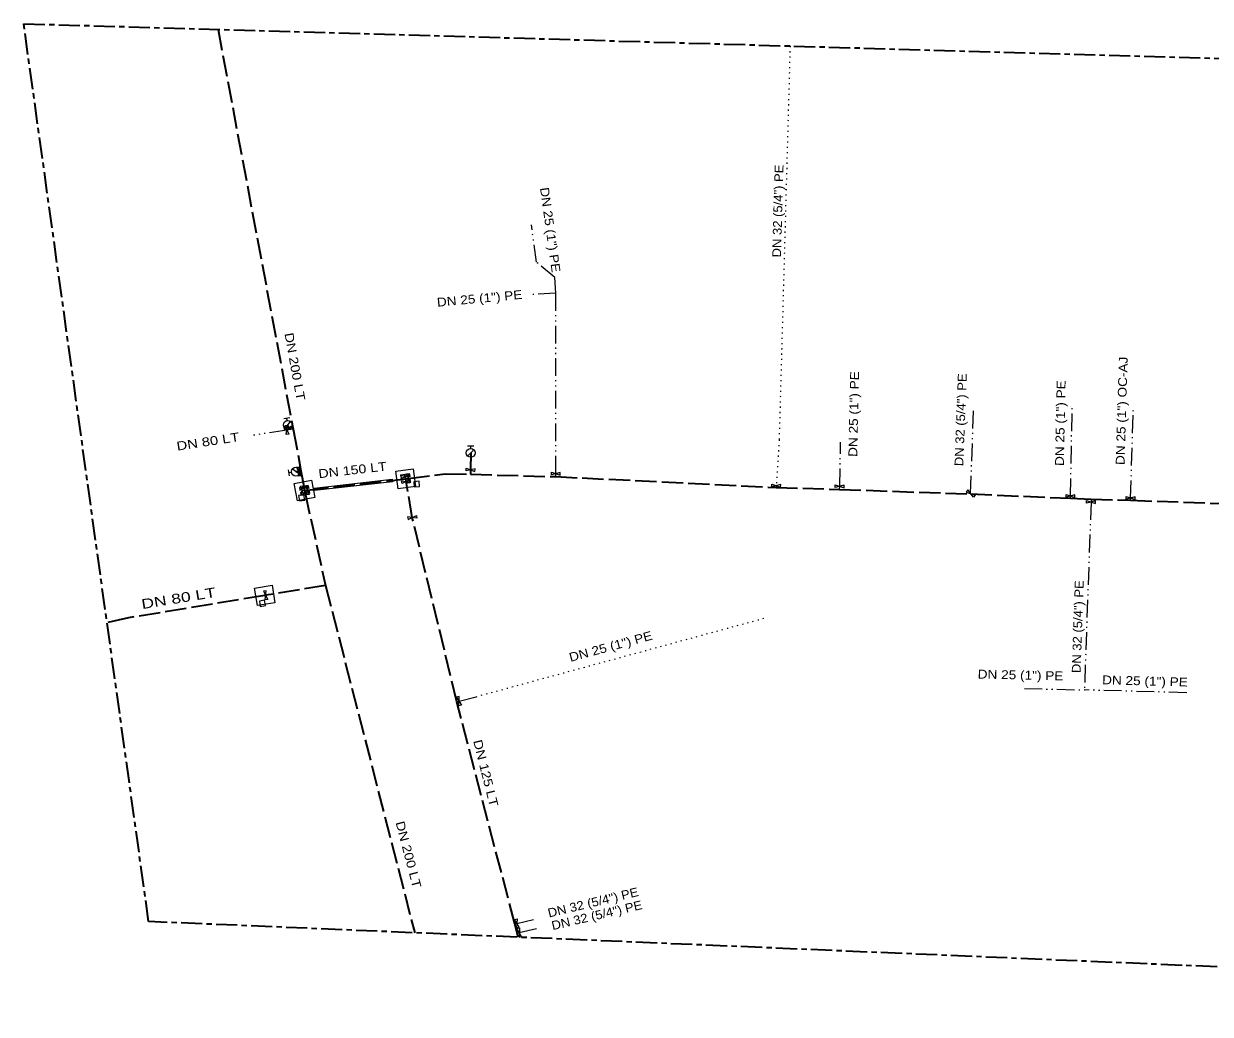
# Model space of a CAD drawing. Extents: x -640241 to -639979, y -1041483 to -1041371.
# Drawn here: x -640241 to -640106.8, y -1041482.8 to -1041370.7 of the extents above; entities that cross this region are included whole.
import ezdxf
from ezdxf.enums import TextEntityAlignment as Align

# ---------------------------------------------------------------- set-up
doc = ezdxf.new("R2010")
doc.units = 0
doc.header["$LTSCALE"] = 0.4
for name, pattern in [('DASH_DOUBLE_DOT', [9.2, 5, -1.2, 0.3, -1.2, 0.3, -1.2]), ('DOTTED', [1.5, 0.3, -1.2]), ('LONG_DASH_SHORT_DASH', [9.9, 6, -1.2, 1.5, -1.2]), ('LONG_DASHED', [7.5, 6, -1.5])]:
    doc.linetypes.add(name, pattern=pattern)
for name, color, linetype, lineweight in [('1', 7, 'LONG_DASH_SHORT_DASH', 35), ('10', 7, 'Continuous', 13), ('13', 7, 'Continuous', 13), ('21', 7, 'LONG_DASHED', 35), ('22', 7, 'DASH_DOUBLE_DOT', 35), ('32', 7, 'DASH_DOUBLE_DOT', 13), ('51', 7, 'Continuous', 25)]:
    doc.layers.add(name, color=color, linetype=linetype, lineweight=lineweight)
doc.layers.add('29', color=7, linetype='Continuous')
doc.layers.add('39', color=7, linetype='Continuous')

msp = doc.modelspace()

# ---------------------------------------------------------------- linework, layer by layer
at = {"layer": '1'}
msp.add_lwpolyline([(-639990.066, -1041378.027), (-639979.473, -1041482.75), (-640226.879, -1041472.267), (-640241.004, -1041370.744)], close=True, dxfattribs=at)
at = {"layer": '10'}
for p, q in [((-640211.613, -1041415.38), (-640210.921, -1041415.278)), ((-640211.448, -1041416.523), (-640210.853, -1041415.719)), ((-640211.224, -1041415.626), (-640211.267, -1041415.329)), ((-640190.815, -1041418.47), (-640190.115, -1041418.47)), ((-640190.465, -1041418.77), (-640190.465, -1041418.47)), ((-640190.819, -1041419.624), (-640190.112, -1041418.917)), ((-640209.813, -1041421.681), (-640210.626, -1041421.099)), ((-640210.952, -1041421.866), (-640211.066, -1041421.175)), ((-640210.713, -1041421.472), (-640211.009, -1041421.521)), ((-640198.401, -1041421.751), (-640197.415, -1041421.585)), ((-640198.401, -1041421.751), (-640198.359, -1041421.998)), ((-640197.415, -1041421.585), (-640197.373, -1041421.831))]:
    msp.add_line(p, q, dxfattribs=at)
for points in [[(-640211.554, -1041416.618), (-640210.605, -1041416.182), (-640210.564, -1041416.479), (-640211.596, -1041416.321)], [(-640211.474, -1041416.219), (-640211.026, -1041417.161), (-640211.322, -1041417.207), (-640211.178, -1041416.173)], [(-640209.672, -1041421.824), (-640210.148, -1041420.895), (-640209.853, -1041420.841), (-640209.967, -1041421.879)], [(-640196.959, -1041421.085), (-640196.69, -1041423.067), (-640198.672, -1041423.336), (-640198.941, -1041421.354)], [(-640189.969, -1041421.092), (-640190.991, -1041421.308), (-640190.966, -1041421.009), (-640189.994, -1041421.391)], [(-640210.424, -1041422.727), (-640208.46, -1041422.347), (-640208.08, -1041424.311), (-640210.044, -1041424.691)], [(-640198.334, -1041422.149), (-640197.398, -1041421.686), (-640197.348, -1041421.982), (-640198.384, -1041421.853)], [(-640197.297, -1041422.281), (-640198.233, -1041422.743), (-640198.283, -1041422.447), (-640197.247, -1041422.577)], [(-640197.734, -1041421.696), (-640197.306, -1041422.648), (-640197.603, -1041422.687), (-640197.436, -1041421.657)], [(-640180.335, -1041421.481), (-640181.346, -1041421.739), (-640181.334, -1041421.439), (-640180.347, -1041421.781)], [(-640209.77, -1041423.468), (-640208.84, -1041422.993), (-640208.786, -1041423.288), (-640209.824, -1041423.173)], [(-640209.755, -1041423.085), (-640209.343, -1041424.043), (-640209.641, -1041424.078), (-640209.457, -1041423.05)], [(-640209.664, -1041424.047), (-640208.734, -1041423.572), (-640208.68, -1041423.867), (-640209.718, -1041423.752)], [(-640209.153, -1041423.004), (-640208.741, -1041423.964), (-640209.039, -1041423.998), (-640208.855, -1041422.97)], [(-640155.414, -1041422.861), (-640156.426, -1041423.118), (-640156.413, -1041422.819), (-640155.427, -1041423.161)], [(-640148.244, -1041422.921), (-640149.256, -1041423.178), (-640149.243, -1041422.879), (-640148.257, -1041423.221)], [(-640134.431, -1041423.699), (-640133.446, -1041424.041), (-640133.621, -1041424.283), (-640134.257, -1041423.456)], [(-640122.145, -1041424.029), (-640123.155, -1041424.292), (-640123.144, -1041423.992), (-640122.156, -1041424.329)], [(-640119.825, -1041424.709), (-640120.835, -1041424.972), (-640120.825, -1041424.672), (-640119.836, -1041425.008)], [(-640115.344, -1041424.248), (-640116.355, -1041424.511), (-640116.344, -1041424.211), (-640115.355, -1041424.548)], [(-640197.554, -1041426.798), (-640196.605, -1041426.362), (-640196.564, -1041426.659), (-640197.596, -1041426.501)], [(-640212.926, -1041434.247), (-640212.602, -1041436.22), (-640214.575, -1041436.544), (-640214.899, -1041434.571)], [(-640213.878, -1041434.909), (-640213.42, -1041435.847), (-640213.716, -1041435.896), (-640213.582, -1041434.861)], [(-640192.061, -1041446.897), (-640191.517, -1041447.789), (-640191.808, -1041447.865), (-640191.77, -1041446.821)], [(-640184.982, -1041472.918), (-640185.517, -1041472.021), (-640185.226, -1041471.948), (-640185.273, -1041472.991)], [(-640184.706, -1041473.957), (-640185.241, -1041473.06), (-640184.95, -1041472.987), (-640184.997, -1041474.03)]]:
    msp.add_lwpolyline(points, close=True, dxfattribs=at)
for centre in [(-640211.1497, -1041416.1199), (-640190.4648, -1041419.2697), (-640210.2203, -1041421.3897)]:
    msp.add_circle(centre, 0.5, dxfattribs=at)
at = {"layer": '13'}
for points in [[(-640196.307, -1041422.475), (-640196.905, -1041422.526), (-640196.854, -1041423.125), (-640196.256, -1041423.074)], [(-640209.921, -1041424.097), (-640209.833, -1041424.691), (-640209.239, -1041424.603), (-640209.327, -1041424.009)], [(-640214.355, -1041436.033), (-640214.257, -1041436.625), (-640213.665, -1041436.527), (-640213.763, -1041435.935)]]:
    msp.add_lwpolyline(points, close=True, dxfattribs=at)
at = {"layer": '21'}
for p, q in [((-640219.038, -1041371.382), (-640210.549, -1041416.582)), ((-640210.549, -1041416.582), (-640209.655, -1041421.313)), ((-640209.655, -1041421.313), (-640209.305, -1041423.23)), ((-640208.947, -1041423.484), (-640197.816, -1041422.211)), ((-640197.816, -1041422.211), (-640197.52, -1041422.172)), ((-640190.492, -1041421.694), (-640180.844, -1041421.96)), ((-640180.844, -1041421.96), (-640155.929, -1041423.19)), ((-640209.252, -1041423.519), (-640209.199, -1041423.81)), ((-640209.199, -1041423.81), (-640206.881, -1041434.267)), ((-640197.08, -1041426.58), (-640197.765, -1041422.512)), ((-640155.929, -1041423.19), (-640148.76, -1041423.4)), ((-640133.941, -1041423.919), (-640122.655, -1041424.41)), ((-640115.856, -1041424.63), (-640094.129, -1041425.38)), ((-640192.029, -1041447.406), (-640197.08, -1041426.58)), ((-640206.881, -1041434.267), (-640213.649, -1041435.378)), ((-640206.881, -1041434.267), (-640196.798, -1041473.542)), ((-640185.493, -1041472.529), (-640192.029, -1041447.406)), ((-640185.217, -1041473.566), (-640185.493, -1041472.529)), ((-640185.085, -1041474.038), (-640185.217, -1041473.566))]:
    msp.add_line(p, q, dxfattribs=at)
for points in [[(-640210.22, -1041421.39), (-640209.91, -1041421.36), (-640209.655, -1041421.313)], [(-640197.765, -1041422.512), (-640197.816, -1041422.211), (-640197.866, -1041421.918), (-640197.908, -1041421.668)], [(-640197.52, -1041422.172), (-640193.35, -1041421.621), (-640190.492, -1041421.694)], [(-640209.305, -1041423.23), (-640209.252, -1041423.519), (-640208.947, -1041423.484)], [(-640148.76, -1041423.4), (-640133.941, -1041423.919), (-640133.941, -1041423.919)], [(-640122.655, -1041424.41), (-640120.317, -1041424.49), (-640115.856, -1041424.63)], [(-640213.75, -1041435.395), (-640229.145, -1041437.922), (-640231.583, -1041438.457)], [(-640213.649, -1041435.378), (-640213.75, -1041435.395), (-640213.75, -1041435.395)]]:
    msp.add_lwpolyline(points, dxfattribs=at)
at = {"layer": '22'}
msp.add_lwpolyline([(-640190.465, -1041419.27), (-640190.48, -1041421.2), (-640190.492, -1041421.694)], dxfattribs=at)
at = {"layer": '32'}
for p, q in [((-640180.837, -1041401.216), (-640183.661, -1041401.361)), ((-640133.939, -1041423.87), (-640133.616, -1041414.435)), ((-640122.65, -1041424.16), (-640122.46, -1041413.945)), ((-640115.85, -1041424.38), (-640115.539, -1041414.234)), ((-640211.25, -1041416.69), (-640215.027, -1041417.271)), ((-640148.75, -1041423.05), (-640148.638, -1041418.065)), ((-640209.393, -1041423.54), (-640209.549, -1041423.564)), ((-640209.252, -1041423.519), (-640209.393, -1041423.54)), ((-640148.76, -1041423.4), (-640148.75, -1041423.05)), ((-640133.941, -1041423.919), (-640133.939, -1041423.87)), ((-640122.655, -1041424.41), (-640122.65, -1041424.16)), ((-640120.33, -1041424.84), (-640121.074, -1041446.077)), ((-640120.317, -1041424.49), (-640120.33, -1041424.84)), ((-640115.856, -1041424.63), (-640115.85, -1041424.38)), ((-640127.863, -1041445.925), (-640121.074, -1041446.077)), ((-640109.515, -1041446.394), (-640121.074, -1041446.077)), ((-640185.25, -1041472.47), (-640183.375, -1041472.018)), ((-640184.974, -1041473.509), (-640183.018, -1041473.048))]:
    msp.add_line(p, q, dxfattribs=at)
at = {"layer": '32', "linetype": 'DOTTED'}
for p, q in [((-640155.92, -1041422.99), (-640155.929, -1041423.19)), ((-640189.852, -1041446.837), (-640157.089, -1041437.912))]:
    msp.add_line(p, q, dxfattribs=at)
msp.add_lwpolyline([(-640154.356, -1041373.259), (-640155.593, -1041417.783), (-640155.92, -1041422.99)], dxfattribs=at)
at = {"layer": '32'}
for points in [[(-640180.837, -1041401.216), (-640180.95, -1041399.438), (-640183.02, -1041397.712), (-640183.611, -1041393.474)], [(-640180.844, -1041421.96), (-640180.84, -1041421.61), (-640180.837, -1041401.216)], [(-640211.04, -1041416.658), (-640211.25, -1041416.69), (-640211.25, -1041416.69)], [(-640211.15, -1041416.12), (-640211.08, -1041416.4), (-640211.04, -1041416.658)], [(-640210.549, -1041416.582), (-640211.04, -1041416.658), (-640211.04, -1041416.658)], [(-640192.029, -1041447.406), (-640191.789, -1041447.343), (-640189.852, -1041446.837)], [(-640185.493, -1041472.529), (-640185.344, -1041472.493), (-640185.25, -1041472.47)], [(-640185.217, -1041473.566), (-640185.083, -1041473.535), (-640184.974, -1041473.509)]]:
    msp.add_lwpolyline(points, dxfattribs=at)
at = {"layer": '51'}
msp.add_lwpolyline([(-640208.166, -1041423.247), (-640199.336, -1041422.247), (-640199.302, -1041422.534), (-640208.123, -1041423.539)], close=True, dxfattribs=at)

# ---------------------------------------------------------------- texts
at = {"layer": '29'}
for s, height, rotation, width, p in [('DN 200 LT', 1, 280.247, 1.2, (-640210.8322, -1041409.5981)), ('DN 150 LT', 1, 6.525, 1.2, (-640203.7708, -1041421.7013)), ('DN 80 LT', 1.1, 9.365, 1.35, (-640223.4105, -1041436.2446)), ('DN 125 LT', 1, 284.153, 1.2, (-640189.2453, -1041455.6047)), ('DN 200 LT', 1, 284.736, 1.2, (-640197.9822, -1041464.8158))]:
    msp.add_text(s, height=height, rotation=rotation, dxfattribs=dict(at, width=width)).set_placement(p, align=Align.CENTER)
at = {"layer": '39'}
for s, rotation, width, p in [('DN 32 (5/4") PE', 88.408, 1.1, (-640155.2408, -1041391.9359)), ('DN 25 (1") PE', 277.939, 1.15, (-640181.9646, -1041394.1159)), ('DN 25 (1") PE', 5.369, 1.15, (-640189.4138, -1041402.2973)), ('DN 25 (1") OC-AJ', 88.244, 1.15, (-640116.361, -1041414.5303)), ('DN 25 (1") PE', 88.713, 1.15, (-640146.6629, -1041414.8902)), ('DN 32 (5/4") PE', 87.822, 1.1, (-640134.5776, -1041415.545)), ('DN 25 (1") PE', 88.82, 1.15, (-640123.3075, -1041415.9143)), ('DN 80 LT', 8.745, 1.25, (-640220.103, -1041418.4782)), ('DN 32 (5/4") PE', 88.048, 1.1, (-640121.333, -1041438.938)), ('DN 25 (1") PE', 15.261, 1.15, (-640174.5086, -1041441.6323)), ('DN 25 (1") PE', 358.717, 1.15, (-640128.3082, -1041444.8877)), ('DN 25 (1") PE', 358.429, 1.15, (-640114.2437, -1041445.5594)), ('DN 32 (5/4") PE', 13.554, 1.1, (-640176.5142, -1041470.5836)), ('DN 32 (5/4") PE', 13.262, 1.1, (-640176.0877, -1041472.0349))]:
    msp.add_text(s, height=1, rotation=rotation, dxfattribs=dict(at, width=width)).set_placement(p, align=Align.CENTER)

doc.saveas('drawing.dxf')
